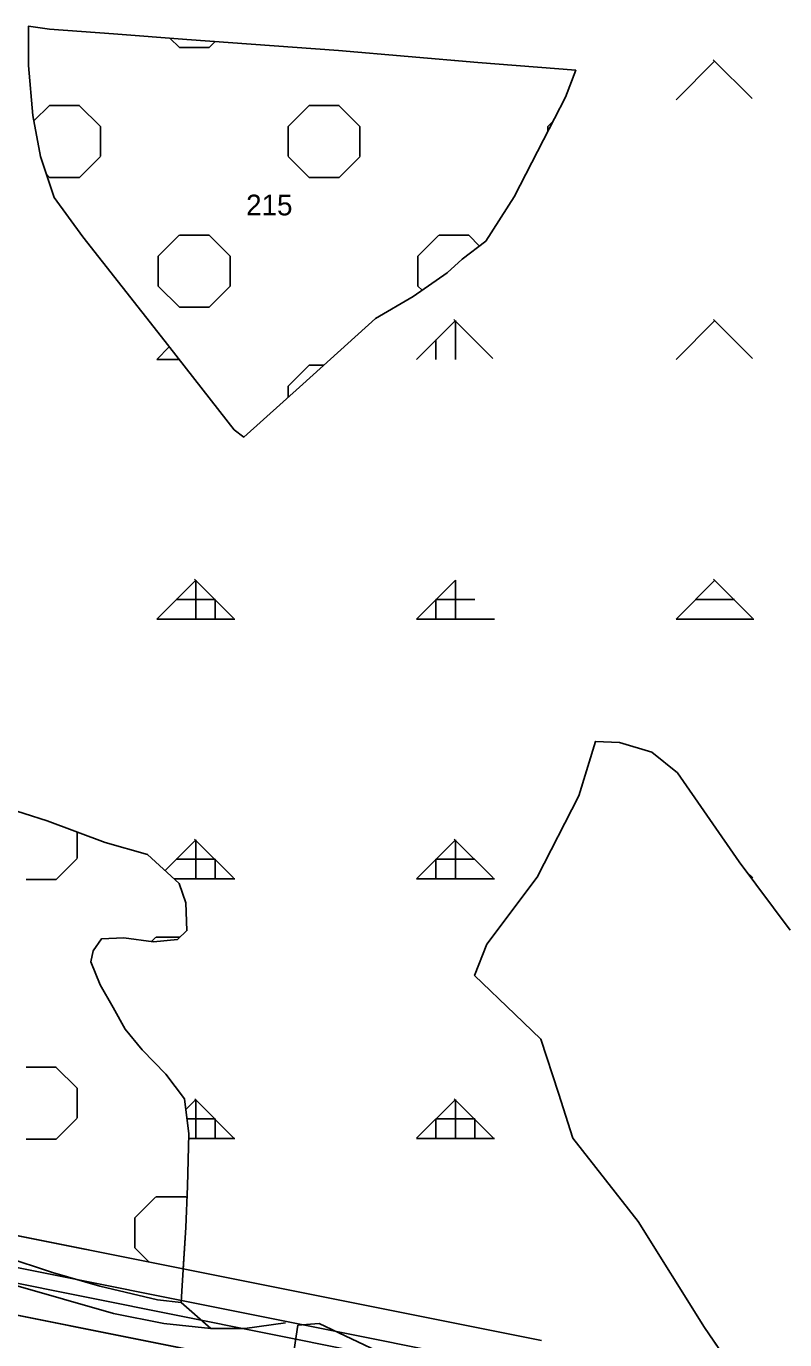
# Model space of a CAD drawing. Extents: x 410727 to 412947, y 4463506 to 4466382.
# Drawn here: x 411830 to 411976.1, y 4465547.1 to 4465800 of the extents above; entities that cross this region are included whole.
import ezdxf

# ---------------------------------------------------------------- set-up
doc = ezdxf.new("R2010")
doc.units = 0
for name, color, linetype in [('ADAKENARI', 7, 'Continuous'), ('KALDIRIM', 7, 'Continuous'), ('KDS_PARSEL_NO', 7, 'Continuous'), ('KDS_PL', 7, 'Continuous'), ('PL_AYA_AGACLANDIRIL', 7, 'Continuous'), ('PL_AYA_ORMAN', 7, 'Continuous'), ('PL_KA_TARIM_DIGER', 7, 'Continuous'), ('TR_AGACALANI', 7, 'Continuous'), ('TR_ORMAN', 7, 'Continuous')]:
    doc.layers.add(name, color=color, linetype=linetype)

msp = doc.modelspace()

# ---------------------------------------------------------------- linework, layer by layer
at = {"layer": 'ADAKENARI'}
for p, q in [((411830.44, 4465800.01), (411830.44, 4465792.43)), ((411834.53, 4465799.44), (411830.44, 4465800.01)), ((411846.84, 4465798.53), (411834.53, 4465799.44)), ((411846.84, 4465798.53), (411834.53, 4465799.44)), ((411860.97, 4465797.46), (411846.84, 4465798.53)), ((411890.13, 4465795.33), (411860.97, 4465797.46)), ((411917.02, 4465793.05), (411890.13, 4465795.33)), ((411830.44, 4465792.43), (411831.31, 4465782.8)), ((411935.86, 4465791.53), (411917.02, 4465793.05)), ((411933.88, 4465786.35), (411935.86, 4465791.53)), ((411929.63, 4465778.13), (411933.88, 4465786.35)), ((411831.31, 4465782.8), (411832.77, 4465774.92)), ((411924.01, 4465767.17), (411929.63, 4465778.13)), ((411832.77, 4465774.92), (411835.39, 4465767.05)), ((411835.39, 4465767.05), (411840.92, 4465759.46)), ((411918.54, 4465758.65), (411924.01, 4465767.17)), ((411840.92, 4465759.46), (411856.06, 4465740.21)), ((411913.98, 4465755.15), (411918.54, 4465758.65)), ((411911.1, 4465752.56), (411913.98, 4465755.15)), ((411904.57, 4465747.99), (411911.1, 4465752.56)), ((411897.27, 4465743.73), (411904.57, 4465747.99)), ((411883.3, 4465731.1), (411897.27, 4465743.73)), ((411856.06, 4465740.21), (411870.08, 4465722.27)), ((411871.9, 4465720.9), (411883.3, 4465731.1)), ((411870.08, 4465722.27), (411871.9, 4465720.9)), ((411939.62, 4465662.31), (411936.43, 4465651.8)), ((411944.25, 4465662.1), (411939.62, 4465662.31)), ((411950.53, 4465660.25), (411944.25, 4465662.1)), ((411950.53, 4465660.25), (411944.25, 4465662.1)), ((411955.47, 4465656.23), (411950.53, 4465660.25)), ((411967.3, 4465639.14), (411955.47, 4465656.23)), ((411834.08, 4465647.01), (411825.23, 4465649.86)), ((411936.43, 4465651.8), (411928.41, 4465636.16)), ((411845.2, 4465642.81), (411834.08, 4465647.01)), ((411853.37, 4465640.53), (411845.2, 4465642.81)), ((411859.5, 4465634.96), (411853.37, 4465640.53)), ((411977.17, 4465625.96), (411967.3, 4465639.14)), ((411860.75, 4465631.21), (411859.5, 4465634.96)), ((411928.41, 4465636.16), (411918.74, 4465623.29)), ((411860.98, 4465625.86), (411860.75, 4465631.21)), ((411844.52, 4465624.27), (411848.83, 4465624.5)), ((411848.83, 4465624.5), (411854.51, 4465623.7)), ((411859.16, 4465624.16), (411860.98, 4465625.86)), ((411842.48, 4465619.84), (411842.93, 4465622)), ((411842.93, 4465622), (411844.52, 4465624.27)), ((411854.51, 4465623.7), (411859.16, 4465624.16)), ((411918.74, 4465623.29), (411916.37, 4465617.22)), ((411844.29, 4465615.4), (411842.48, 4465619.84)), ((411916.37, 4465617.22), (411924.09, 4465609.8)), ((411846.79, 4465611.08), (411844.29, 4465615.4)), ((411849.06, 4465606.87), (411846.79, 4465611.08)), ((411924.09, 4465609.8), (411929.13, 4465604.96)), ((411852.35, 4465602.89), (411849.06, 4465606.87)), ((411929.13, 4465604.96), (411932.52, 4465594.57)), ((411856.89, 4465598.23), (411852.35, 4465602.89)), ((411860.52, 4465593.46), (411856.89, 4465598.23)), ((411932.52, 4465594.57), (411935.3, 4465585.92)), ((411861.32, 4465586.75), (411860.52, 4465593.46)), ((411861.09, 4465576.63), (411861.32, 4465586.75)), ((411935.3, 4465585.92), (411947.85, 4465569.86)), ((411860.75, 4465568.67), (411861.09, 4465576.63)), ((411947.85, 4465569.86), (411960.61, 4465549.47)), ((411860.27, 4465560.72), (411822.91, 4465568.19)), ((411860.27, 4465560.72), (411860.75, 4465568.67)), ((411929.27, 4465546.92), (411860.27, 4465560.72)), ((411819.96, 4465553.48), (411926.33, 4465532.21)), ((411819.96, 4465553.48), (411926.33, 4465532.21)), ((411960.61, 4465549.47), (411975.01, 4465528.47))]:
    msp.add_line(p, q, dxfattribs=at)
at = {"layer": 'KALDIRIM'}
for p, q in [((411821.73, 4465562.31), (411928.09, 4465541.03)), ((411821.14, 4465559.37), (411927.51, 4465538.09))]:
    msp.add_line(p, q, dxfattribs=at)
at = {"layer": 'KDS_PL'}
for p, q in [((411830.44, 4465800.01), (411830.44, 4465792.43)), ((411834.53, 4465799.44), (411830.44, 4465800.01)), ((411846.84, 4465798.53), (411834.53, 4465799.44)), ((411860.97, 4465797.46), (411846.84, 4465798.53)), ((411890.13, 4465795.33), (411860.97, 4465797.46)), ((411917.02, 4465793.05), (411890.13, 4465795.33)), ((411830.44, 4465792.43), (411831.31, 4465782.8)), ((411935.86, 4465791.53), (411917.02, 4465793.05)), ((411933.88, 4465786.35), (411935.86, 4465791.53)), ((411929.63, 4465778.13), (411933.88, 4465786.35)), ((411831.31, 4465782.8), (411832.77, 4465774.92)), ((411924.01, 4465767.17), (411929.63, 4465778.13)), ((411832.77, 4465774.92), (411835.39, 4465767.05)), ((411835.39, 4465767.05), (411840.92, 4465759.46)), ((411918.54, 4465758.65), (411924.01, 4465767.17)), ((411840.92, 4465759.46), (411856.06, 4465740.21)), ((411913.98, 4465755.15), (411918.54, 4465758.65)), ((411911.1, 4465752.56), (411913.98, 4465755.15)), ((411904.57, 4465747.99), (411911.1, 4465752.56)), ((411897.27, 4465743.73), (411904.57, 4465747.99)), ((411883.3, 4465731.1), (411897.27, 4465743.73)), ((411856.06, 4465740.21), (411870.08, 4465722.27)), ((411871.9, 4465720.9), (411883.3, 4465731.1)), ((411870.08, 4465722.27), (411871.9, 4465720.9)), ((411939.62, 4465662.31), (411936.43, 4465651.8)), ((411944.25, 4465662.1), (411939.62, 4465662.31)), ((411950.53, 4465660.25), (411944.25, 4465662.1)), ((411955.47, 4465656.23), (411950.53, 4465660.25)), ((411967.3, 4465639.14), (411955.47, 4465656.23)), ((411825.23, 4465649.86), (411834.08, 4465647.01)), ((411936.43, 4465651.8), (411928.41, 4465636.16)), ((411834.08, 4465647.01), (411845.2, 4465642.81)), ((411845.2, 4465642.81), (411853.37, 4465640.53)), ((411853.37, 4465640.53), (411859.5, 4465634.96)), ((411977.17, 4465625.96), (411967.3, 4465639.14)), ((411859.5, 4465634.96), (411860.75, 4465631.21)), ((411928.41, 4465636.16), (411918.74, 4465623.29)), ((411860.75, 4465631.21), (411860.98, 4465625.86)), ((411848.83, 4465624.5), (411844.52, 4465624.27)), ((411854.51, 4465623.7), (411848.83, 4465624.5)), ((411860.98, 4465625.86), (411859.16, 4465624.16)), ((411842.93, 4465622), (411842.48, 4465619.84)), ((411844.52, 4465624.27), (411842.93, 4465622)), ((411859.16, 4465624.16), (411854.51, 4465623.7)), ((411918.74, 4465623.29), (411916.37, 4465617.22)), ((411842.48, 4465619.84), (411844.29, 4465615.4)), ((411916.37, 4465617.22), (411924.09, 4465609.8)), ((411844.29, 4465615.4), (411846.79, 4465611.08)), ((411846.79, 4465611.08), (411849.06, 4465606.87)), ((411924.09, 4465609.8), (411929.13, 4465604.96)), ((411849.06, 4465606.87), (411852.35, 4465602.89)), ((411929.13, 4465604.96), (411932.52, 4465594.57)), ((411852.35, 4465602.89), (411856.89, 4465598.23)), ((411856.89, 4465598.23), (411860.52, 4465593.46)), ((411932.52, 4465594.57), (411935.3, 4465585.92)), ((411860.52, 4465593.46), (411861.32, 4465586.75)), ((411861.32, 4465586.75), (411861.09, 4465576.63)), ((411935.3, 4465585.92), (411947.85, 4465569.86)), ((411861.09, 4465576.63), (411860.75, 4465568.67)), ((411947.85, 4465569.86), (411960.61, 4465549.47)), ((411860.75, 4465568.67), (411860.07, 4465557.52)), ((411835.1, 4465560.03), (411825.8, 4465563.1)), ((411844.18, 4465557.41), (411835.1, 4465560.03)), ((411827.58, 4465557.64), (411846.83, 4465552.17)), ((411855.3, 4465554.79), (411844.18, 4465557.41)), ((411860.07, 4465557.52), (411859.84, 4465554.23)), ((411859.84, 4465554.23), (411855.3, 4465554.79)), ((411859.84, 4465554.23), (411865.56, 4465549.28)), ((411846.83, 4465552.17), (411856.5, 4465550.21)), ((411856.5, 4465550.21), (411865.56, 4465549.28)), ((411865.56, 4465549.28), (411872.15, 4465549.28)), ((411869.65, 4465467.6), (411882.34, 4465549.88)), ((411872.15, 4465549.28), (411879.97, 4465550.31)), ((411882.34, 4465549.88), (411886.43, 4465550.24)), ((411886.43, 4465550.24), (411907.97, 4465540.04)), ((411960.61, 4465549.47), (411975.01, 4465528.47))]:
    msp.add_line(p, q, dxfattribs=at)
at = {"layer": 'PL_AYA_AGACLANDIRIL'}
msp.add_lwpolyline([(411860.97, 4465797.46), (411890.13, 4465795.33), (411917.02, 4465793.05), (411935.86, 4465791.53), (411933.88, 4465786.35), (411929.63, 4465778.13), (411924.01, 4465767.17), (411918.54, 4465758.65), (411913.98, 4465755.15), (411911.1, 4465752.56), (411904.57, 4465747.99), (411897.27, 4465743.73), (411883.3, 4465731.1), (411871.9, 4465720.9), (411870.08, 4465722.27), (411856.06, 4465740.21), (411840.92, 4465759.46), (411835.39, 4465767.05), (411832.77, 4465774.92), (411831.31, 4465782.8), (411830.44, 4465792.43), (411830.44, 4465800.01), (411834.53, 4465799.44), (411846.84, 4465798.53)], close=True, dxfattribs=at)
msp.add_lwpolyline([(411825.23, 4465649.86), (411834.08, 4465647.01), (411845.2, 4465642.81), (411853.37, 4465640.53), (411859.5, 4465634.96), (411860.75, 4465631.21), (411860.98, 4465625.86), (411859.16, 4465624.16), (411854.51, 4465623.7), (411848.83, 4465624.5), (411844.52, 4465624.27), (411842.93, 4465622), (411842.48, 4465619.84), (411844.29, 4465615.4), (411846.79, 4465611.08), (411849.06, 4465606.87), (411852.35, 4465602.89), (411856.89, 4465598.23), (411860.52, 4465593.46), (411861.32, 4465586.75), (411861.09, 4465576.63), (411860.75, 4465568.67), (411860.27, 4465560.72), (411822.91, 4465568.19)], dxfattribs=at)
at = {"layer": 'PL_AYA_ORMAN'}
for points in [[(411933.88, 4465786.35), (411929.63, 4465778.13), (411924.01, 4465767.17), (411918.54, 4465758.65), (411913.98, 4465755.15), (411911.1, 4465752.56), (411904.57, 4465747.99), (411897.27, 4465743.73), (411883.3, 4465731.1), (411871.9, 4465720.9), (411870.08, 4465722.27), (411856.06, 4465740.21), (411840.92, 4465759.46), (411835.39, 4465767.05), (411832.77, 4465774.92), (411831.31, 4465782.8), (411830.44, 4465792.43), (411830.44, 4465800.01), (411834.53, 4465799.44), (411846.84, 4465798.53), (411860.97, 4465797.46), (411890.13, 4465795.33), (411917.02, 4465793.05), (411935.86, 4465791.53), (411933.88, 4465786.35)], [(411975.01, 4465528.47), (411960.61, 4465549.47), (411947.85, 4465569.86), (411935.3, 4465585.92), (411932.52, 4465594.57), (411929.13, 4465604.96), (411924.09, 4465609.8), (411916.37, 4465617.22), (411918.74, 4465623.29), (411928.41, 4465636.16), (411936.43, 4465651.8), (411939.62, 4465662.31), (411944.25, 4465662.1), (411950.53, 4465660.25), (411955.47, 4465656.23), (411967.3, 4465639.14), (411977.17, 4465625.96)], [(411825.23, 4465649.86), (411834.08, 4465647.01), (411845.2, 4465642.81), (411853.37, 4465640.53), (411859.5, 4465634.96), (411860.75, 4465631.21), (411860.98, 4465625.86), (411859.16, 4465624.16), (411854.51, 4465623.7), (411848.83, 4465624.5), (411844.52, 4465624.27), (411842.93, 4465622), (411842.48, 4465619.84), (411844.29, 4465615.4), (411846.79, 4465611.08), (411849.06, 4465606.87), (411852.35, 4465602.89), (411856.89, 4465598.23), (411860.52, 4465593.46), (411861.32, 4465586.75), (411861.09, 4465576.63), (411860.75, 4465568.67), (411860.27, 4465560.72), (411929.27, 4465546.92)]]:
    msp.add_lwpolyline(points, dxfattribs=at)
at = {"layer": 'PL_KA_TARIM_DIGER'}
for points in [[(411975.01, 4465528.47), (411960.61, 4465549.47), (411947.85, 4465569.86), (411935.3, 4465585.92), (411932.52, 4465594.57), (411929.13, 4465604.96), (411924.09, 4465609.8), (411916.37, 4465617.22), (411918.74, 4465623.29), (411928.41, 4465636.16), (411936.43, 4465651.8), (411939.62, 4465662.31), (411944.25, 4465662.1), (411950.53, 4465660.25), (411955.47, 4465656.23), (411967.3, 4465639.14), (411977.17, 4465625.96)], [(411926.33, 4465532.21), (411819.96, 4465553.48)]]:
    msp.add_lwpolyline(points, dxfattribs=at)
at = {"layer": 'TR_AGACALANI'}
for p, q in [((411859.52, 4465795.9), (411857.71, 4465797.71)), ((411865.26, 4465795.9), (411866.42, 4465797.06)), ((411859.52, 4465795.9), (411865.26, 4465795.9)), ((411831.5, 4465781.78), (411834.5, 4465784.78)), ((411834.52, 4465784.76), (411840.26, 4465784.76)), ((411844.3, 4465780.72), (411840.24, 4465784.77)), ((411880.44, 4465780.72), (411884.5, 4465784.78)), ((411884.52, 4465784.76), (411890.26, 4465784.76)), ((411894.3, 4465780.72), (411890.24, 4465784.77)), ((411930.44, 4465780.72), (411931.54, 4465781.83)), ((411844.3, 4465774.98), (411844.3, 4465780.72)), ((411880.44, 4465774.98), (411880.44, 4465780.72)), ((411894.3, 4465774.98), (411894.3, 4465780.72)), ((411930.44, 4465779.69), (411930.44, 4465780.72)), ((411840.26, 4465770.9), (411844.32, 4465774.96)), ((411884.52, 4465770.9), (411880.46, 4465774.96)), ((411890.26, 4465770.9), (411894.32, 4465774.96)), ((411834.52, 4465770.9), (411833.9, 4465771.52)), ((411834.52, 4465770.9), (411840.26, 4465770.9)), ((411884.52, 4465770.9), (411890.26, 4465770.9)), ((411855.44, 4465755.72), (411859.5, 4465759.78)), ((411859.52, 4465759.76), (411865.26, 4465759.76)), ((411869.3, 4465755.72), (411865.24, 4465759.77)), ((411905.44, 4465755.72), (411909.5, 4465759.78)), ((411909.52, 4465759.76), (411915.26, 4465759.76)), ((411917.31, 4465757.7), (411915.24, 4465759.77)), ((411855.44, 4465749.98), (411855.44, 4465755.72)), ((411869.3, 4465749.98), (411869.3, 4465755.72)), ((411905.44, 4465749.98), (411905.44, 4465755.72)), ((411859.52, 4465745.9), (411855.46, 4465749.96)), ((411865.26, 4465745.9), (411869.32, 4465749.96)), ((411906.25, 4465749.17), (411905.46, 4465749.96)), ((411859.52, 4465745.9), (411865.26, 4465745.9)), ((411880.44, 4465730.72), (411884.5, 4465734.78)), ((411884.52, 4465734.76), (411887.35, 4465734.76)), ((411880.44, 4465728.54), (411880.44, 4465730.72)), ((411839.81, 4465639.8), (411839.81, 4465644.84)), ((411835.77, 4465635.72), (411839.83, 4465639.78)), ((411830.03, 4465635.72), (411835.77, 4465635.72)), ((411854.16, 4465623.75), (411855.01, 4465624.6)), ((411855.03, 4465624.58), (411859.61, 4465624.58)), ((411830.03, 4465599.58), (411835.77, 4465599.58)), ((411839.81, 4465595.53), (411835.75, 4465599.59)), ((411839.81, 4465589.8), (411839.81, 4465595.54)), ((411835.77, 4465585.72), (411839.83, 4465589.78)), ((411830.03, 4465585.72), (411835.77, 4465585.72)), ((411850.95, 4465570.54), (411855.01, 4465574.6)), ((411855.03, 4465574.58), (411860.77, 4465574.58)), ((411860.99, 4465574.35), (411860.75, 4465574.59)), ((411850.95, 4465564.8), (411850.95, 4465570.54)), ((411853.72, 4465562.03), (411850.97, 4465564.78))]:
    msp.add_line(p, q, dxfattribs=at)
at = {"layer": 'TR_ORMAN'}
for p, q in [((411912.48, 4465793.43), (411912.34, 4465793.58)), ((411955.16, 4465785.84), (411962.66, 4465793.34)), ((411969.83, 4465786.08), (411962.33, 4465793.58)), ((411969.83, 4465786.08), (411962.33, 4465793.58)), ((411905.16, 4465735.84), (411912.66, 4465743.34)), ((411919.87, 4465736.06), (411912.37, 4465743.55)), ((411912.67, 4465735.86), (411912.67, 4465743.36)), ((411955.16, 4465735.85), (411962.66, 4465743.35)), ((411969.86, 4465736.06), (411962.36, 4465743.55)), ((411855.17, 4465735.84), (411857.58, 4465738.26)), ((411908.92, 4465735.86), (411908.92, 4465739.61)), ((411855.17, 4465735.86), (411859.46, 4465735.86)), ((411855.17, 4465685.84), (411862.66, 4465693.34)), ((411855.17, 4465685.84), (411862.66, 4465693.34)), ((411869.91, 4465686.03), (411862.41, 4465693.53)), ((411869.91, 4465686.03), (411862.41, 4465693.53)), ((411862.67, 4465685.86), (411862.67, 4465693.36)), ((411862.67, 4465685.86), (411862.67, 4465693.36)), ((411905.16, 4465685.85), (411912.66, 4465693.35)), ((411912.67, 4465685.86), (411912.67, 4465693.36)), ((411955.16, 4465685.86), (411962.66, 4465693.36)), ((411969.89, 4465686.03), (411962.39, 4465693.53)), ((411858.92, 4465689.61), (411866.42, 4465689.61)), ((411858.92, 4465689.61), (411866.42, 4465689.61)), ((411866.42, 4465685.86), (411866.42, 4465689.61)), ((411866.42, 4465685.86), (411866.42, 4465689.61)), ((411908.92, 4465685.86), (411908.92, 4465689.61)), ((411908.92, 4465689.61), (411916.42, 4465689.61)), ((411958.92, 4465689.61), (411966.42, 4465689.61)), ((411855.17, 4465685.86), (411870.17, 4465685.86)), ((411855.17, 4465685.86), (411870.17, 4465685.86)), ((411905.17, 4465685.86), (411920.17, 4465685.86)), ((411955.17, 4465685.86), (411970.17, 4465685.86)), ((411856.76, 4465637.45), (411862.66, 4465643.35)), ((411856.76, 4465637.45), (411862.66, 4465643.35)), ((411869.94, 4465636.01), (411862.44, 4465643.51)), ((411869.94, 4465636.01), (411862.44, 4465643.51)), ((411862.67, 4465635.86), (411862.67, 4465643.36)), ((411862.67, 4465635.86), (411862.67, 4465643.36)), ((411905.16, 4465635.86), (411912.66, 4465643.36)), ((411905.16, 4465635.86), (411912.66, 4465643.36)), ((411919.93, 4465636.01), (411912.43, 4465643.51)), ((411919.93, 4465636.01), (411912.43, 4465643.51)), ((411912.67, 4465635.86), (411912.67, 4465643.36)), ((411912.67, 4465635.86), (411912.67, 4465643.36)), ((411858.92, 4465639.61), (411866.42, 4465639.61)), ((411858.92, 4465639.61), (411866.42, 4465639.61)), ((411866.42, 4465635.86), (411866.42, 4465639.61)), ((411866.42, 4465635.86), (411866.42, 4465639.61)), ((411908.92, 4465635.86), (411908.92, 4465639.61)), ((411908.92, 4465639.61), (411916.42, 4465639.61)), ((411908.92, 4465635.86), (411908.92, 4465639.61)), ((411908.92, 4465639.61), (411916.42, 4465639.61)), ((411969.92, 4465636.01), (411968.81, 4465637.12)), ((411969.92, 4465636.01), (411968.81, 4465637.12)), ((411858.51, 4465635.86), (411870.17, 4465635.86)), ((411858.51, 4465635.86), (411870.17, 4465635.86)), ((411905.17, 4465635.86), (411920.17, 4465635.86)), ((411905.17, 4465635.86), (411920.17, 4465635.86)), ((411860.76, 4465591.45), (411862.66, 4465593.36)), ((411860.76, 4465591.45), (411862.66, 4465593.36)), ((411869.97, 4465585.98), (411862.47, 4465593.48)), ((411869.97, 4465585.98), (411862.47, 4465593.48)), ((411862.67, 4465585.86), (411862.67, 4465593.36)), ((411862.67, 4465585.86), (411862.67, 4465593.36)), ((411905.16, 4465585.87), (411912.66, 4465593.36)), ((411905.16, 4465585.87), (411912.66, 4465593.36)), ((411919.96, 4465585.98), (411912.46, 4465593.48)), ((411919.96, 4465585.98), (411912.46, 4465593.48)), ((411912.67, 4465585.86), (411912.67, 4465593.36)), ((411912.67, 4465585.86), (411912.67, 4465593.36)), ((411860.98, 4465589.61), (411866.42, 4465589.61)), ((411860.98, 4465589.61), (411866.42, 4465589.61)), ((411866.42, 4465585.86), (411866.42, 4465589.61)), ((411866.42, 4465585.86), (411866.42, 4465589.61)), ((411908.92, 4465585.86), (411908.92, 4465589.61)), ((411908.92, 4465589.61), (411916.42, 4465589.61)), ((411908.92, 4465585.86), (411908.92, 4465589.61)), ((411908.92, 4465589.61), (411916.42, 4465589.61)), ((411916.42, 4465585.86), (411916.42, 4465589.61)), ((411916.42, 4465585.86), (411916.42, 4465589.61)), ((411861.3, 4465585.86), (411870.17, 4465585.86)), ((411861.3, 4465585.86), (411870.17, 4465585.86)), ((411905.17, 4465585.86), (411920.17, 4465585.86)), ((411905.17, 4465585.86), (411920.17, 4465585.86))]:
    msp.add_line(p, q, dxfattribs=at)

# ---------------------------------------------------------------- texts
at = {"layer": 'KDS_PARSEL_NO'}
msp.add_text('215', height=4, dxfattribs=at).set_placement((411872.37, 4465763.59))

doc.saveas('drawing.dxf')
